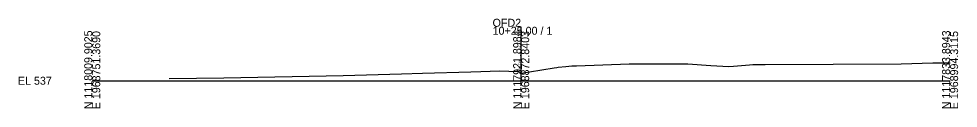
# Model space of a CAD drawing. Extents: x 9974 to 10303, y 9990 to 12021.
# Drawn here: x 9974.3 to 10302.8, y 9990.3 to 10021.8 of the extents above; entities that cross this region are included whole.
import ezdxf

# ---------------------------------------------------------------- set-up
doc = ezdxf.new("R2010")
doc.units = 0
for name, color, linetype in [('Level 10', 7, 'Continuous'), ('Level 60', 7, 'Continuous'), ('Level 63', 7, 'Continuous')]:
    doc.layers.add(name, color=color, linetype=linetype)

msp = doc.modelspace()

# ---------------------------------------------------------------- linework, layer by layer
at = {"layer": 'Level 60'}
for p, q in [((10152.87, 10003.08), (10161.52, 10004.52)), ((10161.52, 10004.52), (10162.45, 10004.68)), ((10162.45, 10004.68), (10162.89, 10004.72)), ((10162.89, 10004.72), (10165.58, 10004.98)), ((10165.58, 10004.98), (10167.74, 10005.2)), ((10167.74, 10005.2), (10169.39, 10005.26)), ((10169.39, 10005.26), (10187.73, 10005.97)), ((10187.73, 10005.97), (10191.49, 10005.96)), ((10191.49, 10005.96), (10199.28, 10005.95)), ((10199.28, 10005.95), (10201.76, 10005.94)), ((10201.76, 10005.94), (10202.93, 10005.94)), ((10202.93, 10005.94), (10203.7, 10005.94)), ((10203.7, 10005.94), (10208.3, 10005.89)), ((10208.3, 10005.89), (10216.35, 10005.36)), ((10216.35, 10005.36), (10222.6, 10004.95)), ((10222.6, 10004.95), (10224.22, 10005.09)), ((10224.22, 10005.09), (10229.85, 10005.56)), ((10229.85, 10005.56), (10231.06, 10005.66)), ((10231.06, 10005.66), (10231.38, 10005.69)), ((10231.38, 10005.69), (10235.32, 10005.69)), ((10235.32, 10005.69), (10282.91, 10005.9)), ((10282.91, 10005.9), (10293.94, 10006.27)), ((10293.94, 10006.27), (10299.23, 10006.32)), ((10299.23, 10006.32), (10300, 10006.33)), ((10026.94, 10000.83), (10045.99, 10001.07)), ((10045.99, 10001.07), (10087.8, 10001.87)), ((10087.8, 10001.87), (10108.19, 10002.45)), ((10108.19, 10002.45), (10115.54, 10002.67)), ((10115.54, 10002.67), (10132.35, 10003.17)), ((10132.35, 10003.17), (10135.95, 10003.27)), ((10135.95, 10003.27), (10142.46, 10003.47)), ((10142.46, 10003.47), (10148.96, 10003.22)), ((10148.96, 10003.22), (10150.12, 10002.68)), ((10150.12, 10002.68), (10152.87, 10003.08))]:
    msp.add_line(p, q, dxfattribs=at)
at = {"layer": 'Level 63'}
for p, q in [((10150, 10000), (10150, 10018.98)), ((10000, 10000), (10150, 10000)), ((10150, 10000), (10300, 10000))]:
    msp.add_line(p, q, dxfattribs=at)

# ---------------------------------------------------------------- texts
at = {"layer": 'Level 10'}
msp.add_text('539.739', height=0.8, rotation=90, dxfattribs=at).set_placement((10149.9, 10003.24))
at = {"layer": 'Level 63'}
for s, p in [('OFD2', (10140, 10018.98)), ('10+25.00 / 1', (10140, 10016.18)), ('EL 537', (9974, 9998.6))]:
    msp.add_text(s, height=2.8, dxfattribs=at).set_placement(p)
for s, p in [('N 1118009.9025', (10000, 9990)), ('E 1968751.3690', (10002.8, 9990)), ('N 1117921.8984', (10150, 9990)), ('E 1968872.8403', (10152.8, 9990)), ('N 1117833.8943', (10300, 9990)), ('E 1968994.3115', (10302.8, 9990))]:
    msp.add_text(s, height=2.8, rotation=90, dxfattribs=at).set_placement(p)

doc.saveas('drawing.dxf')
